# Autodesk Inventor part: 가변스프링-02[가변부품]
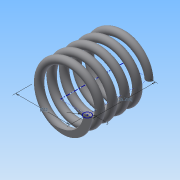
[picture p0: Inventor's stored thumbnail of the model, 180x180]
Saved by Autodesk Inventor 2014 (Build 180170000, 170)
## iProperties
Created: 2015-09
Part Number: 가변스프링-02[가변부품]
Material: 강철, 탄소
Document SubType Name: Modeling
Designer: study
Density: 7.87 g/cm^3
Appearance: 반연마
Mass: 18.6318 g
Surface Area: 32.4192 cm^2
Volume: 2.36745 cm^3
Author: study
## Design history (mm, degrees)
sketch "스케치1"
  geometry: L1 (0, 0)-(11, 0); L2 (11, 0)-(11, 25.358); L3 (11, 25.358)-(0, 25.358); L4 (0, 25.358)-(0, 0); C1 r 1.5 at (11, 0)
  constraints: 8 end point, 2 parallel, 1 centre point, 1 coincident, 1 horizontal, 1 perpendicular
  dimensions: "d0" = 25.35829 distance of L1.end L2.end (derived); "d1" = 22 diameter of L2 L4; "d2" = 3 diameter of C1
feature "코일1" sketch "스케치1" pitch "d3" = 10; turns "d5" = 5; dims "d4" = 25.35829 (= d0), "d6" = 0, angle "d7" = 90 deg, angle "d8" = 90 deg, "d9" = 0, "d10" = 0
node "작업 평면1"
sketch "스케치2"
  geometry: L1 (-12.5, 0)-(-9.5, 0) reference; 1 further point
  constraints: 1 horizontal alignment
extrude "돌출1" cut sketch "스케치2" stored distance "d12" = 10; taper "d13" = 0 deg
node "작업 평면2"
sketch "스케치3"
  geometry: L1 (-9.5, 0)-(-12.5, 0) reference; 1 further point
  constraints: 1 horizontal alignment
extrude "돌출2" cut sketch "스케치3" stored distance "d15" = 10; taper "d16" = 0 deg
node "솔리드1"
node "절단 모서리 투영1"
node "절단 모서리 투영2"
other parameters: "d11" = 0, "d14" = 25.35829 (= d0)
